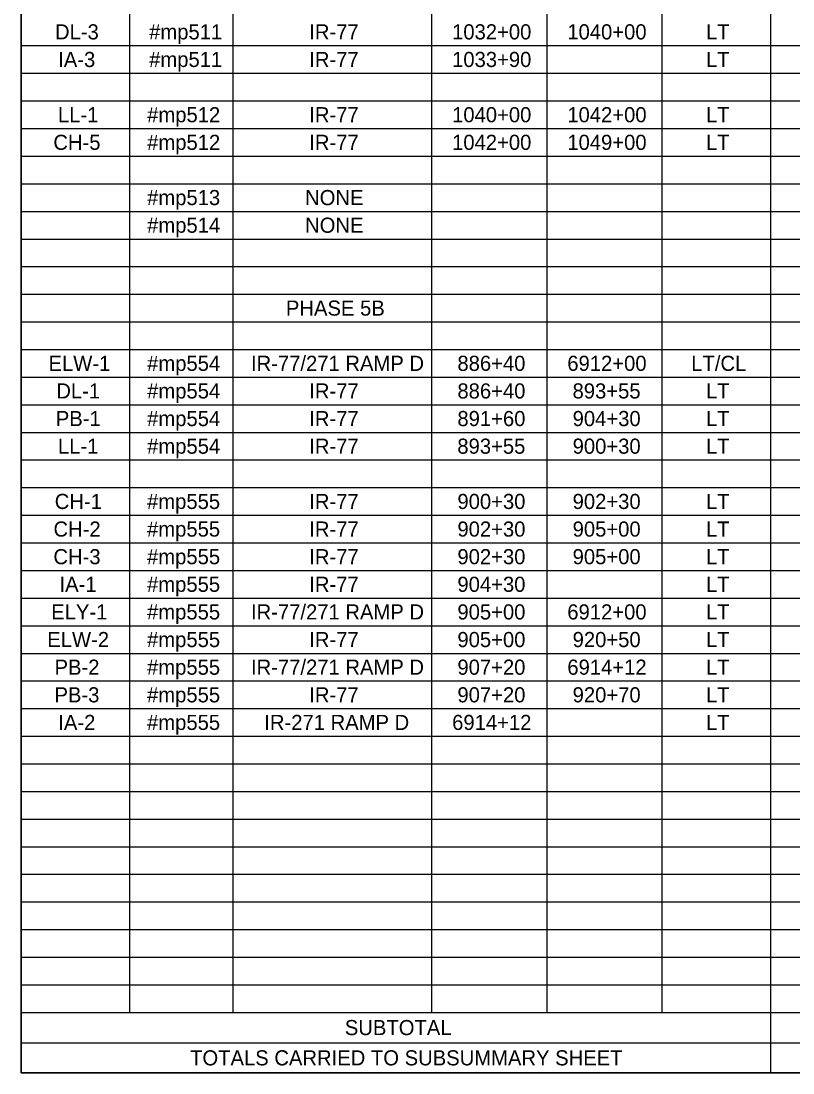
# Model space of a CAD drawing. Extents: x 91011267 to 91022583, y 37007614 to 37014266.
# Drawn here: x 91014538 to 91014922, y 37007614 to 37008137 of the extents above; entities that cross this region are included whole.
import ezdxf

# ---------------------------------------------------------------- set-up
doc = ezdxf.new("R2010")
doc.units = 0
doc.layers.add('SC_Scratch2', color=7, linetype='Continuous')
doc.layers.add('SH_Data', color=7, linetype='Continuous')

msp = doc.modelspace()

# ---------------------------------------------------------------- linework, layer by layer
at = {"layer": 'SC_Scratch2'}
msp.add_lwpolyline([(91014537.63, 37008663.81), (91016062.63, 37008663.81), (91016062.63, 37007613.81), (91014537.63, 37007613.81)], close=True, dxfattribs=at)
at = {"layer": 'SH_Data'}
for p, q in [((91014537.63, 37008289.61), (91014537.63, 37008083.53)), ((91014591.67, 37008289.61), (91014591.67, 37008083.53)), ((91014643.08, 37008289.61), (91014643.08, 37008083.53)), ((91014741.93, 37008289.61), (91014741.93, 37008083.53)), ((91014799.27, 37008289.61), (91014799.27, 37008083.53)), ((91014856.6, 37008289.61), (91014856.6, 37008083.53)), ((91014910.64, 37008289.61), (91014910.64, 37008083.53)), ((91014537.63, 37008124.75), (91014856.6, 37008124.75)), ((91014856.6, 37008124.75), (91014910.64, 37008124.75)), ((91014910.64, 37008124.75), (91015211.16, 37008124.75)), ((91014537.63, 37008111.01), (91014856.6, 37008111.01)), ((91014856.6, 37008111.01), (91014910.64, 37008111.01)), ((91014910.64, 37008111.01), (91015211.16, 37008111.01)), ((91014537.63, 37008097.27), (91014856.6, 37008097.27)), ((91014856.6, 37008097.27), (91014910.64, 37008097.27)), ((91014910.64, 37008097.27), (91015211.16, 37008097.27)), ((91014537.63, 37008083.53), (91014856.6, 37008083.53)), ((91014537.63, 37008083.53), (91014537.63, 37008069.79)), ((91014591.67, 37008083.53), (91014591.67, 37008069.79)), ((91014643.08, 37008083.53), (91014643.08, 37008069.79)), ((91014741.93, 37008083.53), (91014741.93, 37008069.79)), ((91014799.27, 37008083.53), (91014799.27, 37008069.79)), ((91014856.6, 37008083.53), (91014910.64, 37008083.53)), ((91014856.6, 37008083.53), (91014856.6, 37008069.79)), ((91014910.64, 37008083.53), (91015211.16, 37008083.53)), ((91014910.64, 37008083.53), (91014910.64, 37008069.79)), ((91014537.63, 37008069.79), (91014856.6, 37008069.79)), ((91014537.63, 37008069.79), (91014537.63, 37008056.05)), ((91014591.67, 37008069.79), (91014591.67, 37008056.05)), ((91014643.08, 37008069.79), (91014643.08, 37008056.05)), ((91014741.93, 37008069.79), (91014741.93, 37008056.05)), ((91014799.27, 37008069.79), (91014799.27, 37008056.05)), ((91014856.6, 37008069.79), (91014910.64, 37008069.79)), ((91014856.6, 37008069.79), (91014856.6, 37008056.05)), ((91014910.64, 37008069.79), (91015211.16, 37008069.79)), ((91014910.64, 37008069.79), (91014910.64, 37008056.05)), ((91014537.63, 37008056.05), (91014856.6, 37008056.05)), ((91014537.63, 37008056.05), (91014537.63, 37008014.84)), ((91014591.67, 37008056.05), (91014591.67, 37008014.84)), ((91014643.08, 37008056.05), (91014643.08, 37008014.84)), ((91014741.93, 37008056.05), (91014741.93, 37008014.84)), ((91014799.27, 37008056.05), (91014799.27, 37008014.84)), ((91014856.6, 37008056.05), (91014910.64, 37008056.05)), ((91014856.6, 37008056.05), (91014856.6, 37008014.84)), ((91014910.64, 37008056.05), (91015211.16, 37008056.05)), ((91014910.64, 37008056.05), (91014910.64, 37008014.84)), ((91014537.63, 37008042.32), (91014856.6, 37008042.32)), ((91014856.6, 37008042.32), (91014910.64, 37008042.32)), ((91014910.64, 37008042.32), (91015211.16, 37008042.32)), ((91014537.63, 37008028.58), (91014856.6, 37008028.58)), ((91014856.6, 37008028.58), (91014910.64, 37008028.58)), ((91014910.64, 37008028.58), (91015211.16, 37008028.58)), ((91014537.63, 37008014.84), (91014856.6, 37008014.84)), ((91014537.63, 37008014.84), (91014537.63, 37008001.1)), ((91014591.67, 37008014.84), (91014591.67, 37008001.1)), ((91014643.08, 37008014.84), (91014643.08, 37008001.1)), ((91014741.93, 37008014.84), (91014741.93, 37008001.1)), ((91014799.27, 37008014.84), (91014799.27, 37008001.1)), ((91014856.6, 37008014.84), (91014910.64, 37008014.84)), ((91014856.6, 37008014.84), (91014856.6, 37008001.1)), ((91014910.64, 37008014.84), (91015211.16, 37008014.84)), ((91014910.64, 37008014.84), (91014910.64, 37008001.1)), ((91014537.63, 37008001.1), (91014856.6, 37008001.1)), ((91014537.63, 37008001.1), (91014537.63, 37007987.36)), ((91014591.67, 37008001.1), (91014591.67, 37007987.36)), ((91014643.08, 37008001.1), (91014643.08, 37007987.36)), ((91014741.93, 37008001.1), (91014741.93, 37007987.36)), ((91014799.27, 37008001.1), (91014799.27, 37007987.36)), ((91014856.6, 37008001.1), (91014910.64, 37008001.1)), ((91014856.6, 37008001.1), (91014856.6, 37007987.36)), ((91014910.64, 37008001.1), (91015211.16, 37008001.1)), ((91014910.64, 37008001.1), (91014910.64, 37007987.36)), ((91014537.63, 37007987.36), (91014856.6, 37007987.36)), ((91014537.63, 37007987.36), (91014537.63, 37007946.15)), ((91014591.67, 37007987.36), (91014591.67, 37007946.15)), ((91014643.08, 37007987.36), (91014643.08, 37007946.15)), ((91014741.93, 37007987.36), (91014741.93, 37007946.15)), ((91014799.27, 37007987.36), (91014799.27, 37007946.15)), ((91014856.6, 37007987.36), (91014910.64, 37007987.36)), ((91014856.6, 37007987.36), (91014856.6, 37007946.15)), ((91014910.64, 37007987.36), (91015211.16, 37007987.36)), ((91014910.64, 37007987.36), (91014910.64, 37007946.15)), ((91014537.63, 37007973.62), (91014856.6, 37007973.62)), ((91014856.6, 37007973.62), (91014910.64, 37007973.62)), ((91014910.64, 37007973.62), (91015211.16, 37007973.62)), ((91014537.63, 37007959.89), (91014856.6, 37007959.89)), ((91014856.6, 37007959.89), (91014910.64, 37007959.89)), ((91014910.64, 37007959.89), (91015211.16, 37007959.89)), ((91014537.63, 37007946.15), (91014856.6, 37007946.15)), ((91014537.63, 37007946.15), (91014537.63, 37007932.41)), ((91014591.67, 37007946.15), (91014591.67, 37007932.41)), ((91014643.08, 37007946.15), (91014643.08, 37007932.41)), ((91014741.93, 37007946.15), (91014741.93, 37007932.41)), ((91014799.27, 37007946.15), (91014799.27, 37007932.41)), ((91014856.6, 37007946.15), (91014910.64, 37007946.15)), ((91014856.6, 37007946.15), (91014856.6, 37007932.41)), ((91014910.64, 37007946.15), (91015211.16, 37007946.15)), ((91014910.64, 37007946.15), (91014910.64, 37007932.41)), ((91014537.63, 37007932.41), (91014856.6, 37007932.41)), ((91014537.63, 37007932.41), (91014537.63, 37007918.67)), ((91014591.67, 37007932.41), (91014591.67, 37007918.67)), ((91014643.08, 37007932.41), (91014643.08, 37007918.67)), ((91014741.93, 37007932.41), (91014741.93, 37007918.67)), ((91014799.27, 37007932.41), (91014799.27, 37007918.67)), ((91014856.6, 37007932.41), (91014910.64, 37007932.41)), ((91014856.6, 37007932.41), (91014856.6, 37007918.67)), ((91014910.64, 37007932.41), (91015211.16, 37007932.41)), ((91014910.64, 37007932.41), (91014910.64, 37007918.67)), ((91014537.63, 37007918.67), (91014856.6, 37007918.67)), ((91014537.63, 37007918.67), (91014537.63, 37007613.81)), ((91014591.67, 37007918.67), (91014591.67, 37007643.9)), ((91014643.08, 37007918.67), (91014643.08, 37007643.9)), ((91014741.93, 37007918.67), (91014741.93, 37007643.9)), ((91014799.27, 37007918.67), (91014799.27, 37007643.9)), ((91014856.6, 37007918.67), (91014910.64, 37007918.67)), ((91014856.6, 37007918.67), (91014856.6, 37007643.9)), ((91014910.64, 37007918.67), (91015211.16, 37007918.67)), ((91014910.64, 37007918.67), (91014910.64, 37007613.81)), ((91014537.63, 37007904.93), (91014856.6, 37007904.93)), ((91014856.6, 37007904.93), (91014910.64, 37007904.93)), ((91014910.64, 37007904.93), (91015211.16, 37007904.93)), ((91014537.63, 37007891.19), (91014856.6, 37007891.19)), ((91014856.6, 37007891.19), (91014910.64, 37007891.19)), ((91014910.64, 37007891.19), (91015211.16, 37007891.19)), ((91014537.63, 37007877.46), (91014856.6, 37007877.46)), ((91014856.6, 37007877.46), (91014910.64, 37007877.46)), ((91014910.64, 37007877.46), (91015211.16, 37007877.46)), ((91014537.63, 37007863.72), (91014856.6, 37007863.72)), ((91014856.6, 37007863.72), (91014910.64, 37007863.72)), ((91014910.64, 37007863.72), (91015211.16, 37007863.72)), ((91014537.63, 37007849.98), (91014856.6, 37007849.98)), ((91014856.6, 37007849.98), (91014910.64, 37007849.98)), ((91014910.64, 37007849.98), (91015211.16, 37007849.98)), ((91014537.63, 37007836.24), (91014856.6, 37007836.24)), ((91014856.6, 37007836.24), (91014910.64, 37007836.24)), ((91014910.64, 37007836.24), (91015211.16, 37007836.24)), ((91014537.63, 37007822.5), (91014856.6, 37007822.5)), ((91014856.6, 37007822.5), (91014910.64, 37007822.5)), ((91014910.64, 37007822.5), (91015211.16, 37007822.5)), ((91014537.63, 37007808.76), (91014856.6, 37007808.76)), ((91014856.6, 37007808.76), (91014910.64, 37007808.76)), ((91014910.64, 37007808.76), (91015211.16, 37007808.76)), ((91014537.63, 37007795.03), (91014856.6, 37007795.03)), ((91014856.6, 37007795.03), (91014910.64, 37007795.03)), ((91014910.64, 37007795.03), (91015211.16, 37007795.03)), ((91014537.63, 37007781.29), (91014856.6, 37007781.29)), ((91014856.6, 37007781.29), (91014910.64, 37007781.29)), ((91014910.64, 37007781.29), (91015211.16, 37007781.29)), ((91014537.63, 37007767.55), (91014856.6, 37007767.55)), ((91014856.6, 37007767.55), (91014910.64, 37007767.55)), ((91014910.64, 37007767.55), (91015211.16, 37007767.55)), ((91014537.63, 37007753.81), (91014856.6, 37007753.81)), ((91014856.6, 37007753.81), (91014910.64, 37007753.81)), ((91014910.64, 37007753.81), (91015211.16, 37007753.81)), ((91014537.63, 37007740.07), (91014856.6, 37007740.07)), ((91014856.6, 37007740.07), (91014910.64, 37007740.07)), ((91014910.64, 37007740.07), (91015211.16, 37007740.07)), ((91014537.63, 37007726.33), (91014856.6, 37007726.33)), ((91014856.6, 37007726.33), (91014910.64, 37007726.33)), ((91014910.64, 37007726.33), (91015211.16, 37007726.33)), ((91014537.63, 37007712.6), (91014856.6, 37007712.6)), ((91014856.6, 37007712.6), (91014910.64, 37007712.6)), ((91014910.64, 37007712.6), (91015211.16, 37007712.6)), ((91014537.63, 37007698.86), (91014856.6, 37007698.86)), ((91014856.6, 37007698.86), (91014910.64, 37007698.86)), ((91014910.64, 37007698.86), (91015211.16, 37007698.86)), ((91014537.63, 37007685.12), (91014856.6, 37007685.12)), ((91014856.6, 37007685.12), (91014910.64, 37007685.12)), ((91014910.64, 37007685.12), (91015211.16, 37007685.12)), ((91014537.63, 37007671.38), (91014856.6, 37007671.38)), ((91014856.6, 37007671.38), (91014910.64, 37007671.38)), ((91014910.64, 37007671.38), (91015211.16, 37007671.38)), ((91014537.63, 37007657.64), (91014856.6, 37007657.64)), ((91014856.6, 37007657.64), (91014910.64, 37007657.64)), ((91014910.64, 37007657.64), (91015211.16, 37007657.64)), ((91014537.63, 37007643.9), (91014856.6, 37007643.9)), ((91014856.6, 37007643.9), (91014910.64, 37007643.9)), ((91014910.64, 37007643.9), (91015211.16, 37007643.9)), ((91014537.63, 37007628.86), (91014856.6, 37007628.86)), ((91014856.6, 37007628.86), (91014910.64, 37007628.86)), ((91014910.64, 37007628.86), (91015211.16, 37007628.86)), ((91014537.63, 37007613.81), (91014856.6, 37007613.81)), ((91014856.6, 37007613.81), (91014910.64, 37007613.81)), ((91014910.64, 37007613.81), (91015211.16, 37007613.81))]:
    msp.add_line(p, q, dxfattribs=at)

# ---------------------------------------------------------------- texts
for s, height, p in [('DL-3', 7.523, (91014554.54, 37008127.85)), ('#mp511', 7.523, (91014601.39, 37008127.85)), ('IR-77', 7.523, (91014681.07, 37008127.85)), ('1032+00', 7.523, (91014752.15, 37008127.85)), ('1040+00', 7.523, (91014809.49, 37008127.85)), ('LT', 7.523, (91014878.51, 37008127.85)), ('IA-3', 7.523, (91014556.13, 37008114.12)), ('#mp511', 7.523, (91014601.39, 37008114.12)), ('IR-77', 7.523, (91014681.07, 37008114.12)), ('1033+90', 7.523, (91014752.15, 37008114.12)), ('LT', 7.523, (91014878.51, 37008114.12)), ('LL-1', 7.523, (91014556, 37008086.64)), ('#mp512', 7.523, (91014600.41, 37008086.64)), ('IR-77', 7.523, (91014681.07, 37008086.64)), ('1040+00', 7.523, (91014752.15, 37008086.64)), ('1042+00', 7.523, (91014809.49, 37008086.64)), ('LT', 7.523, (91014878.51, 37008086.64)), ('CH-5', 7.523, (91014553.72, 37008072.9)), ('#mp512', 7.523, (91014600.41, 37008072.9)), ('IR-77', 7.523, (91014681.07, 37008072.9)), ('1042+00', 7.523, (91014752.15, 37008072.9)), ('1049+00', 7.523, (91014809.49, 37008072.9)), ('LT', 7.523, (91014878.51, 37008072.9)), ('#mp513', 7.523, (91014600.38, 37008045.42)), ('NONE', 7.523, (91014678.99, 37008045.42)), ('#mp514', 7.523, (91014600.39, 37008031.69)), ('NONE', 7.523, (91014678.99, 37008031.69)), ('PHASE 5B', 7.523, (91014669.45, 37007990.47)), ('ELW-1', 7.523, (91014551.32, 37007962.99)), ('#mp554', 7.523, (91014600.39, 37007962.99)), ('IR-77/271 RAMP D', 7.5234, (91014652.07, 37007962.99)), ('886+40', 7.523, (91014754.8, 37007962.99)), ('6912+00', 7.523, (91014809.49, 37007962.99)), ('LT/CL', 7.523, (91014871.17, 37007962.99)), ('DL-1', 7.523, (91014555.2, 37007949.26)), ('#mp554', 7.523, (91014600.39, 37007949.26)), ('IR-77', 7.523, (91014681.07, 37007949.26)), ('886+40', 7.523, (91014754.8, 37007949.26)), ('893+55', 7.523, (91014812.1, 37007949.26)), ('LT', 7.523, (91014878.51, 37007949.26)), ('PB-1', 7.523, (91014554.94, 37007935.52)), ('#mp554', 7.523, (91014600.39, 37007935.52)), ('IR-77', 7.523, (91014681.07, 37007935.52)), ('891+60', 7.523, (91014754.8, 37007935.52)), ('904+30', 7.523, (91014812.14, 37007935.52)), ('LT', 7.523, (91014878.51, 37007935.52)), ('LL-1', 7.523, (91014556, 37007921.78)), ('#mp554', 7.523, (91014600.39, 37007921.78)), ('IR-77', 7.523, (91014681.07, 37007921.78)), ('893+55', 7.523, (91014754.76, 37007921.78)), ('900+30', 7.523, (91014812.14, 37007921.78)), ('LT', 7.523, (91014878.51, 37007921.78)), ('CH-1', 7.523, (91014554.41, 37007894.3)), ('#mp555', 7.523, (91014600.35, 37007894.3)), ('IR-77', 7.523, (91014681.07, 37007894.3)), ('900+30', 7.523, (91014754.8, 37007894.3)), ('902+30', 7.523, (91014812.14, 37007894.3)), ('LT', 7.523, (91014878.51, 37007894.3)), ('CH-2', 7.523, (91014553.79, 37007880.56)), ('#mp555', 7.523, (91014600.35, 37007880.56)), ('IR-77', 7.523, (91014681.07, 37007880.56)), ('902+30', 7.523, (91014754.8, 37007880.56)), ('905+00', 7.523, (91014812.14, 37007880.56)), ('LT', 7.523, (91014878.51, 37007880.56)), ('CH-3', 7.523, (91014553.75, 37007866.83)), ('#mp555', 7.523, (91014600.35, 37007866.83)), ('IR-77', 7.523, (91014681.07, 37007866.83)), ('902+30', 7.523, (91014754.8, 37007866.83)), ('905+00', 7.523, (91014812.14, 37007866.83)), ('LT', 7.523, (91014878.51, 37007866.83)), ('IA-1', 7.523, (91014556.79, 37007853.09)), ('#mp555', 7.523, (91014600.35, 37007853.09)), ('IR-77', 7.523, (91014681.07, 37007853.09)), ('904+30', 7.523, (91014754.8, 37007853.09)), ('LT', 7.523, (91014878.51, 37007853.09)), ('ELY-1', 7.523, (91014552.64, 37007839.35)), ('#mp555', 7.523, (91014600.35, 37007839.35)), ('IR-77/271 RAMP D', 7.5234, (91014652.07, 37007839.35)), ('905+00', 7.523, (91014754.8, 37007839.35)), ('6912+00', 7.523, (91014809.49, 37007839.35)), ('LT', 7.523, (91014878.51, 37007839.35)), ('ELW-2', 7.523, (91014550.7, 37007825.61)), ('#mp555', 7.523, (91014600.35, 37007825.61)), ('IR-77', 7.523, (91014681.07, 37007825.61)), ('905+00', 7.523, (91014754.8, 37007825.61)), ('920+50', 7.523, (91014812.14, 37007825.61)), ('LT', 7.523, (91014878.51, 37007825.61)), ('IR-77/271 RAMP D', 7.5234, (91014652.07, 37007811.87)), ('PB-2', 7.523, (91014554.31, 37007811.87)), ('#mp555', 7.523, (91014600.35, 37007811.87)), ('907+20', 7.523, (91014754.8, 37007811.87)), ('6914+12', 7.523, (91014809.51, 37007811.87)), ('LT', 7.523, (91014878.51, 37007811.87)), ('PB-3', 7.523, (91014554.28, 37007798.13)), ('#mp555', 7.523, (91014600.35, 37007798.13)), ('IR-77', 7.523, (91014681.07, 37007798.13)), ('907+20', 7.523, (91014754.8, 37007798.13)), ('920+70', 7.523, (91014812.14, 37007798.13)), ('LT', 7.523, (91014878.51, 37007798.13)), ('IA-2', 7.523, (91014556.17, 37007784.4)), ('#mp555', 7.523, (91014600.35, 37007784.4)), ('IR-271 RAMP D', 7.5234, (91014658.69, 37007784.4)), ('6914+12', 7.523, (91014752.18, 37007784.4)), ('LT', 7.523, (91014878.51, 37007784.4)), ('SUBTOTAL', 7.523, (91014698.78, 37007632.62)), ('TOTALS CARRIED TO SUBSUMMARY SHEET', 7.5234, (91014621.77, 37007617.57))]:
    msp.add_text(s, height=height, dxfattribs=at).set_placement(p)

doc.saveas('drawing.dxf')
